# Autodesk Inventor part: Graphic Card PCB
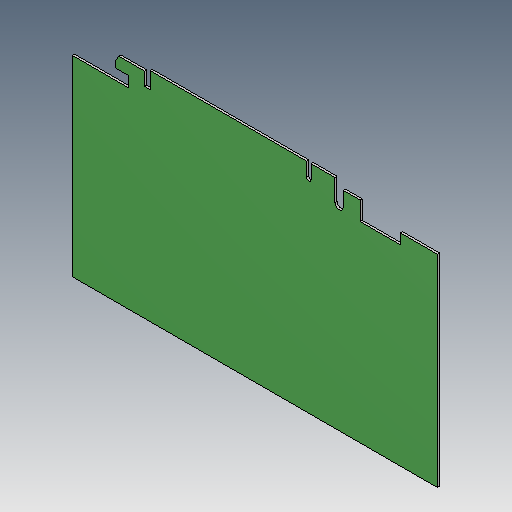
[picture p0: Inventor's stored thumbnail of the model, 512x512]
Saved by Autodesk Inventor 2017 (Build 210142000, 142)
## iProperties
Created: 2005-12
Part Number: Graphic Card PCB
Material: Generic
Document SubType Name: Modeling
Designer: DanielSeverino
Density: 1 g/cm^3
Appearance: Default
Author: DanielSeverino
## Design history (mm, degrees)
feature "Solid1"
body "Solid2"
